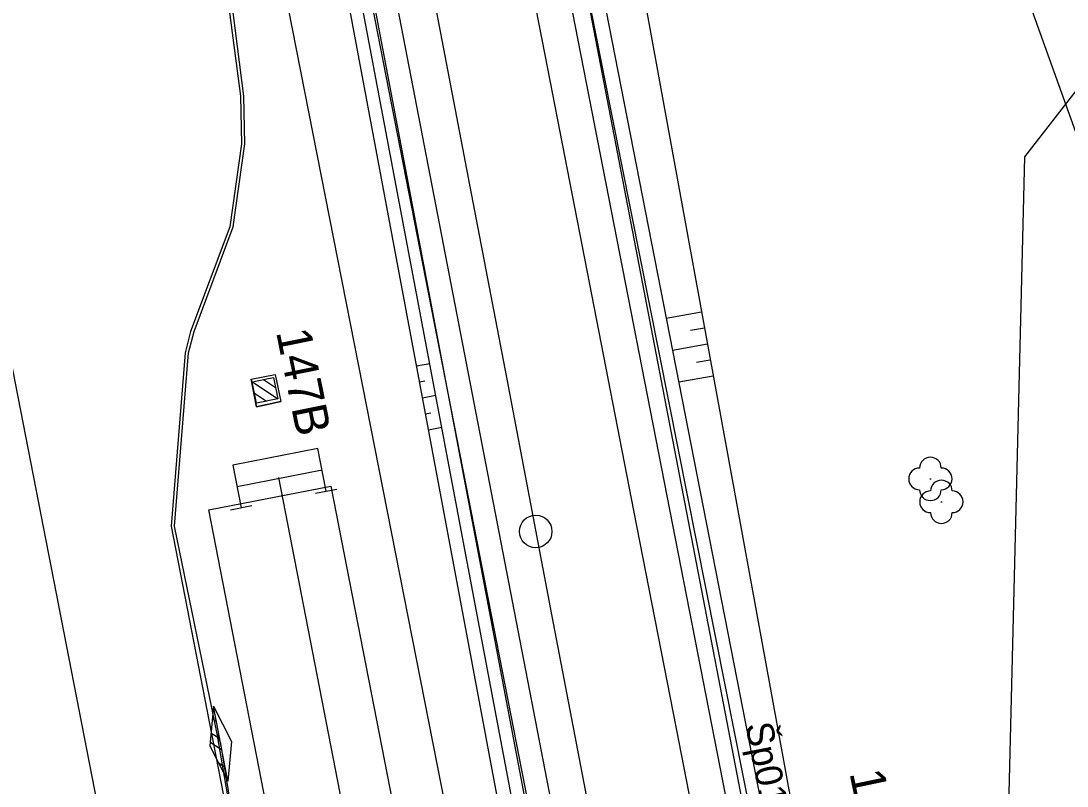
# Model space of a CAD drawing. Extents: x -545967 to -545044, y -1122650 to -1118491.
# Drawn here: x -545744.88 to -545696.59, y -1119193.49 to -1119158.18 of the extents above; entities that cross this region are included whole.
import ezdxf

# ---------------------------------------------------------------- set-up
doc = ezdxf.new("R2010")
doc.units = 0
for name, color, linetype in [('osvětlené plochy-hodnota-obrys', 7, 'Continuous'), ('Vrstva 1', 7, 'Continuous'), ('Vrstva 1 - Koleje', 7, 'Continuous'), ('Vrstva 11 - Trakce', 7, 'Continuous'), ('Vrstva 12 - Trakce zaklady', 7, 'Continuous'), ('Vrstva 15_zarazedla', 7, 'Continuous'), ('Vrstva 19 - Staniceni', 7, 'Continuous'), ('Vrstva 26 - silnoproud', 7, 'Continuous'), ('Vrstva 28 - zabzar', 7, 'Continuous'), ('Vrstva 31', 7, 'Continuous'), ('Vrstva 32', 7, 'Continuous'), ('Vrstva 4 - Teren - stezky - prechody - plochy', 7, 'Continuous'), ('Vrstva 43', 7, 'Continuous'), ('Vrstva 44', 7, 'Continuous'), ('Vrstva 48', 7, 'Continuous'), ('Vrstva 49', 7, 'Continuous'), ('Vrstva 50', 7, 'Continuous'), ('Vrstva 51', 7, 'Continuous')]:
    doc.layers.add(name, color=color, linetype=linetype)

msp = doc.modelspace()

# ---------------------------------------------------------------- linework, layer by layer
at = {"layer": 'osvětlené plochy-hodnota-obrys'}
for points in [[(-545694.33, -1119168.5), (-545707.92, -1119130.607), (-545700.794, -1119127.991)], [(-545664.282, -1119515.639), (-545680.447, -1119467.233), (-545736.202, -1119180.74), (-545730.573, -1119179.645)], [(-545730.573, -1119179.645), (-545675.345, -1119462.605), (-545660.82, -1119505.941)]]:
    msp.add_lwpolyline(points, dxfattribs=at)
at = {"layer": 'Vrstva 1'}
for points in [[(-545771.025, -1119042.195), (-545765.518, -1119070.46), (-545759.655, -1119100.537), (-545754.322, -1119127.883), (-545749.142, -1119154.443), (-545741.38, -1119194.232), (-545736.638, -1119218.552), (-545732.259, -1119241.007)], [(-545732.996, -1119179.254), (-545727.764, -1119206.17), (-545723.954, -1119225.738), (-545721.389, -1119238.891)]]:
    msp.add_lwpolyline(points, dxfattribs=at)
at = {"layer": 'Vrstva 1 - Koleje'}
for points in [[(-545733.999, -1119091.546), (-545732.95, -1119096.936), (-545731.205, -1119105.879), (-545729.373, -1119115.292), (-545728.267, -1119120.965), (-545726.468, -1119130.178), (-545724.605, -1119139.732), (-545722.574, -1119150.154), (-545720.702, -1119159.751), (-545718.638, -1119170.336), (-545716.601, -1119180.775), (-545714.642, -1119190.838), (-545712.795, -1119200.311), (-545711.639, -1119206.25), (-545709.729, -1119216.005), (-545707.216, -1119228.928), (-545705.339, -1119238.544), (-545703.888, -1119245.98)], [(-545738.202, -1119092.228), (-545736.387, -1119101.709), (-545734.567, -1119111.273), (-545732.861, -1119120.206), (-545731.063, -1119129.63), (-545729.36, -1119138.55), (-545727.68, -1119147.349), (-545726.123, -1119155.516), (-545724.233, -1119165.426), (-545722.398, -1119175.037), (-545720.387, -1119185.566), (-545718.546, -1119195.193), (-545717.286, -1119201.759), (-545715.378, -1119211.671), (-545713.882, -1119219.417), (-545712.258, -1119227.812), (-545710.337, -1119237.731), (-545708.555, -1119246.894)]]:
    msp.add_lwpolyline(points, dxfattribs=at)
at = {"layer": 'Vrstva 11 - Trakce'}
for p, q in [((-545733.679, -1119174.732), (-545733.128, -1119175.098)), ((-545734.198, -1119174.837), (-545733.023, -1119175.617)), ((-545734.097, -1119175.355), (-545733.539, -1119175.724))]:
    msp.add_line(p, q, dxfattribs=at)
msp.add_lwpolyline([(-545733.221, -1119174.64), (-545733.023, -1119175.62), (-545734.003, -1119175.818), (-545734.201, -1119174.838)], close=True, dxfattribs=at)
at = {"layer": 'Vrstva 12 - Trakce zaklady'}
msp.add_line((-545734.256, -1119174.719), (-545734.008, -1119175.989), dxfattribs=at)
for points in [[(-545733.138, -1119174.491), (-545732.884, -1119175.747), (-545734.008, -1119175.989), (-545734.256, -1119174.719), (-545733.138, -1119174.491)], [(-545734.256, -1119174.719), (-545734.256, -1119174.719), (-545733.138, -1119174.491)], [(-545733.138, -1119174.491), (-545733.138, -1119174.491), (-545732.884, -1119175.747), (-545732.884, -1119175.747)], [(-545734.008, -1119175.989), (-545734.008, -1119175.989), (-545732.884, -1119175.747)]]:
    msp.add_lwpolyline(points, dxfattribs=at)
at = {"layer": 'Vrstva 15_zarazedla'}
for p, q in [((-545734.906, -1119179.663), (-545730.98, -1119178.899)), ((-545731.28, -1119179.976), (-545730.298, -1119179.786)), ((-545735.206, -1119180.74), (-545734.225, -1119180.549))]:
    msp.add_line(p, q, dxfattribs=at)
msp.add_lwpolyline([(-545730.789, -1119179.881), (-545731.171, -1119177.918), (-545735.097, -1119178.681), (-545734.715, -1119180.644)], dxfattribs=at)
at = {"layer": 'Vrstva 19 - Staniceni'}
msp.add_circle((-545721.118, -1119181.74), 0.75, dxfattribs=at)
at = {"layer": 'Vrstva 26 - silnoproud'}
msp.add_lwpolyline([(-545748.72, -1119088.787), (-545745.498, -1119105.777), (-545744.592, -1119110.019), (-545739.382, -1119138.558), (-545737.893, -1119145.12), (-545736.243, -1119151.98), (-545735.253, -1119157.79), (-545734.753, -1119161.66), (-545734.703, -1119163.85), (-545735.243, -1119167.68), (-545737.053, -1119172.51), (-545737.303, -1119173.49), (-545737.953, -1119181.49), (-545735.153, -1119195.905), (-545734.323, -1119200.74), (-545732.62, -1119201.11)], dxfattribs=at)
at = {"layer": 'Vrstva 28 - zabzar'}
msp.add_lwpolyline([(-545724.371, -1119249.989), (-545724.69, -1119248.61), (-545727.23, -1119235.34), (-545728.99, -1119226.34), (-545732.03, -1119209.67), (-545734.16, -1119200.74), (-545735.82, -1119191.07), (-545737.79, -1119181.49), (-545737.14, -1119173.49), (-545736.89, -1119172.51), (-545735.08, -1119167.68), (-545734.54, -1119163.85), (-545734.59, -1119161.66), (-545735.09, -1119157.79), (-545736.08, -1119151.98), (-545737.73, -1119145.12), (-545739.97, -1119133.32), (-545740.77, -1119128.56), (-545744.45, -1119110.05), (-545745.46, -1119105.77), (-545746.9, -1119097.66), (-545750.31, -1119079.79)], dxfattribs=at)
at = {"layer": 'Vrstva 31'}
msp.add_lwpolyline([(-545724.371, -1119249.989), (-545724.69, -1119248.61), (-545727.23, -1119235.34), (-545728.99, -1119226.34), (-545732.03, -1119209.67), (-545734.16, -1119200.74), (-545735.82, -1119191.07), (-545737.79, -1119181.49), (-545737.14, -1119173.49), (-545736.89, -1119172.51), (-545735.08, -1119167.68), (-545734.54, -1119163.85), (-545734.59, -1119161.66), (-545735.09, -1119157.79), (-545736.08, -1119151.98), (-545737.73, -1119145.12), (-545739.97, -1119133.32), (-545740.77, -1119128.56), (-545744.45, -1119110.05), (-545745.46, -1119105.77), (-545746.9, -1119097.66), (-545750.31, -1119079.79)], dxfattribs=at)
at = {"layer": 'Vrstva 32'}
for p, q in [((-545735.999, -1119189.948), (-545735.953, -1119189.994)), ((-545736.048, -1119190.365), (-545735.858, -1119190.494)), ((-545736.108, -1119191.024), (-545735.704, -1119191.298)), ((-545736.137, -1119191.455), (-545735.605, -1119191.816)), ((-545735.771, -1119192.403), (-545735.452, -1119192.619)), ((-545735.421, -1119193.076), (-545735.357, -1119193.118))]:
    msp.add_line(p, q, dxfattribs=at)
for points in [[(-545724.371, -1119249.989), (-545724.69, -1119248.61), (-545727.23, -1119235.34), (-545728.99, -1119226.34), (-545732.03, -1119209.67), (-545734.16, -1119200.74), (-545735.66, -1119191.53), (-545735.82, -1119191.07), (-545737.79, -1119181.49), (-545737.14, -1119173.49), (-545736.89, -1119172.51), (-545735.08, -1119167.68), (-545734.54, -1119163.85), (-545734.59, -1119161.66), (-545735.09, -1119157.79), (-545736.08, -1119151.98), (-545737.73, -1119145.12), (-545739.97, -1119133.32), (-545740.77, -1119128.56), (-545744.45, -1119110.05), (-545745.46, -1119105.77), (-545746.9, -1119097.66), (-545750.31, -1119079.79)], [(-545735.991, -1119189.799), (-545735.16, -1119191.434), (-545735.329, -1119193.261)]]:
    msp.add_lwpolyline(points, dxfattribs=at)
msp.add_lwpolyline([(-545735.991, -1119189.799), (-545736.16, -1119191.626), (-545735.329, -1119193.261)], close=True, dxfattribs=at)
at = {"layer": 'Vrstva 4 - Teren - stezky - prechody - plochy'}
for points in [[(-545842.991, -1118523.919), (-545841.705, -1118530.396), (-545836.849, -1118554.447), (-545831.054, -1118584.604), (-545819.351, -1118645.264), (-545811.232, -1118686.911), (-545799.532, -1118746.647), (-545788.535, -1118802.768), (-545777.847, -1118857.696), (-545765.826, -1118919.341), (-545755.98, -1118970.183), (-545745.509, -1119023.121), (-545734.813, -1119078.883), (-545723.148, -1119138.675), (-545711.327, -1119199.256), (-545707.51, -1119218.932), (-545706.355, -1119218.803)], [(-545711.324, -1119247.435), (-545711.901, -1119243.963), (-545720.224, -1119201.665), (-545721.285, -1119195.757), (-545731.546, -1119141.712), (-545737.081, -1119112.42), (-545743.441, -1119079.103), (-545754.278, -1119022.005), (-545764.127, -1118971.243), (-545774.702, -1118917.119), (-545786.098, -1118858.181), (-545797.005, -1118803.413), (-545807.661, -1118749.422), (-545819.911, -1118686.431), (-545828.531, -1118641.36), (-545850.15, -1118530.525), (-545851.156, -1118525.517)], [(-545710.225, -1119247.22), (-545719.004, -1119201.386), (-545730.622, -1119141.385), (-545736.208, -1119112.206), (-545742.564, -1119078.927), (-545753.414, -1119021.814), (-545763.359, -1118970.942), (-545773.922, -1118916.709), (-545785.328, -1118858.188), (-545796.206, -1118802.914), (-545806.845, -1118748.63), (-545819.206, -1118686.191), (-545827.818, -1118641.013), (-545849.345, -1118530.249), (-545850.409, -1118525.371)], [(-545787.709, -1118802.92), (-545777.141, -1118857.583), (-545765.122, -1118918.891), (-545755.123, -1118970.549), (-545744.471, -1119024.933), (-545734.117, -1119078.34), (-545722.331, -1119138.405), (-545711.219, -1119196.145), (-545707.543, -1119214.266), (-545707.412, -1119215.197), (-545706.355, -1119218.803)]]:
    msp.add_lwpolyline(points, dxfattribs=at)
at = {"layer": 'Vrstva 44'}
for points in [[(-545744.065, -1119094.166), (-545734.822, -1119146.139), (-545734.752, -1119146.549), (-545734.659, -1119146.89), (-545724.724, -1119197.313), (-545724.661, -1119197.687), (-545724.663, -1119198.006), (-545716.416, -1119241.322), (-545716.376, -1119241.688), (-545716.362, -1119242.059), (-545715.179, -1119248.19)], [(-545730.081, -1119098.833), (-545720.599, -1119147.438), (-545711.114, -1119195.247), (-545720.817, -1119196.365), (-545721.01, -1119196.412)], [(-545739.309, -1119100.743), (-545730.259, -1119149.369), (-545721.097, -1119196.213), (-545721.01, -1119196.412)]]:
    msp.add_lwpolyline(points, dxfattribs=at)
at = {"layer": 'Vrstva 48'}
for p, q in [((-545713.466, -1119171.616), (-545715.09, -1119171.912)), ((-545713.331, -1119172.353), (-545713.977, -1119172.471)), ((-545713.196, -1119173.091), (-545714.801, -1119173.385)), ((-545726.615, -1119174.096), (-545726.01, -1119173.983)), ((-545713.061, -1119173.829), (-545713.699, -1119173.946)), ((-545712.926, -1119174.567), (-545714.513, -1119174.857)), ((-545726.477, -1119174.833), (-545726.234, -1119174.788)), ((-545726.339, -1119175.571), (-545725.731, -1119175.457)), ((-545726.201, -1119176.308), (-545725.957, -1119176.262)), ((-545726.062, -1119177.045), (-545725.453, -1119176.931))]:
    msp.add_line(p, q, dxfattribs=at)
at = {"layer": 'Vrstva 49'}
for points in [[(-545839.308, -1118523.198), (-545838.102, -1118529.579), (-545837.4, -1118533.485), (-545832.706, -1118555.695), (-545825.144, -1118594.377), (-545814.251, -1118651.352), (-545808.026, -1118685.152), (-545795.162, -1118750.192), (-545783.943, -1118809.71), (-545774.848, -1118856.951), (-545763.418, -1118915.038), (-545752.928, -1118968.655), (-545741.707, -1119025.946), (-545730.219, -1119081.986), (-545719.001, -1119141.326), (-545708.857, -1119196.833), (-545704.642, -1119214.146)], [(-545785.57, -1118809.023), (-545776.461, -1118857.744), (-545776.223, -1118859.028), (-545764.986, -1118916.441), (-545764.658, -1118917.886), (-545754.446, -1118970.66), (-545754.175, -1118971.989), (-545744.319, -1119022.631), (-545744.059, -1119023.95), (-545733.435, -1119078.425), (-545721.625, -1119138.52), (-545721.391, -1119139.742), (-545710.151, -1119197.125), (-545709.969, -1119198.727), (-545706.792, -1119214.135), (-545707.412, -1119215.197), (-545706.355, -1119218.803), (-545705.856, -1119218.828), (-545705.109, -1119218.756), (-545703.505, -1119218.63), (-545703.071, -1119219.321), (-545701.68, -1119223.926)], [(-545712.345, -1119247.635), (-545712.918, -1119244.626), (-545721.552, -1119201.108), (-545732.642, -1119141.942), (-545733.194, -1119140.665), (-545738.437, -1119113.17), (-545744.258, -1119082.787), (-545744.781, -1119080.348), (-545754.155, -1119031.651), (-545755.213, -1119026.18), (-545765.268, -1118974.147), (-545765.5, -1118972.759), (-545775.821, -1118920.177), (-545776.085, -1118918.771), (-545787.25, -1118861.285), (-545787.565, -1118859.78), (-545796.822, -1118811.001)], [(-545711.324, -1119247.435), (-545711.901, -1119243.963), (-545720.224, -1119201.665), (-545721.285, -1119195.757), (-545721.943, -1119195.521), (-545732.082, -1119141.82), (-545732.265, -1119140.515), (-545737.739, -1119112.717), (-545743.315, -1119083.132), (-545744.039, -1119079.561), (-545753.263, -1119031.334), (-545754.002, -1119028.935), (-545754.148, -1119025.929), (-545754.487, -1119024.319), (-545754.825, -1119024.298), (-545764.544, -1118973.992), (-545764.787, -1118972.577), (-545775.108, -1118920.03), (-545775.396, -1118918.541), (-545786.585, -1118861.093), (-545786.924, -1118859.548), (-545796.323, -1118810.897)]]:
    msp.add_lwpolyline(points, dxfattribs=at)
at = {"layer": 'Vrstva 50'}
for p, q in [((-545702.932, -1119179.314), (-545702.861, -1119179.314)), ((-545702.426, -1119180.373), (-545702.355, -1119180.373))]:
    msp.add_line(p, q, dxfattribs=at)
for centre, start, end in [((-545702.902, -1119178.813), 0, 180), ((-545703.402, -1119179.313), 90, 270), ((-545702.402, -1119179.313), 270, 90), ((-545702.395, -1119179.872), 0, 180), ((-545702.902, -1119179.813), 180, 0), ((-545702.895, -1119180.372), 90, 270), ((-545701.895, -1119180.372), 270, 90), ((-545702.395, -1119180.872), 180, 0)]:
    msp.add_arc(centre, 0.5, start, end, dxfattribs=at)
at = {"layer": 'Vrstva 51'}
msp.add_lwpolyline([(-545699.471, -1119201.94), (-545698.549, -1119164.446), (-545694.235, -1119158.917), (-545692.241, -1119158.084), (-545688.341, -1119153.091), (-545685.062, -1119149.37), (-545681.978, -1119143.375)], dxfattribs=at)

# ---------------------------------------------------------------- texts
at = {"layer": 'Vrstva 11 - Trakce'}
for s, rotation, p in [('147B', 281.4327, (-545733.109, -1119172.529)), ('148', 281.7807, (-545706.642, -1119192.88))]:
    msp.add_text(s, height=1.6, rotation=rotation, dxfattribs=at).set_placement(p)
at = {"layer": 'Vrstva 43'}
msp.add_text('Šp018', height=1.25, rotation=280.9998, dxfattribs=at).set_placement((-545711.442, -1119190.66))

doc.saveas('drawing.dxf')
